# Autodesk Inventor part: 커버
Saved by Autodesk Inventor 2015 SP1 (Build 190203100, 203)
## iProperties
Created: 2026-07
Part Number: 커버
Material: 일반
Document SubType Name: Modeling
Designer: user
Density: 1 g/cm^3
Appearance: 기본값
Author: user
Author: jhkim
Creation Date: 2026-07-01
Sending System: Autodesk Inventor 2027
Preprocessor: ST-DEVELOPER v20.1
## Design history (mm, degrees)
node "커버1"
node "솔리드1"
node "기준1"
